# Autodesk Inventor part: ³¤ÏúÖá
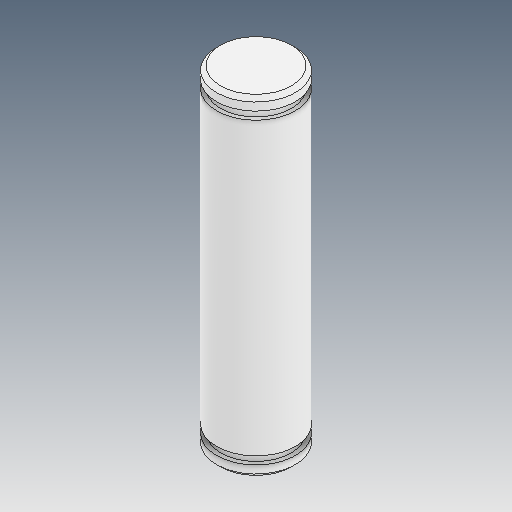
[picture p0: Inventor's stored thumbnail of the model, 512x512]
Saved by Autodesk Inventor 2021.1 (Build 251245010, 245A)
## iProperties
Created: 2021-05
Part Number: ³¤ÏúÖá
Material: Ogólny
Document SubType Name: Modeling
Designer: user
Density: 1 g/cm^3
Appearance: Domyślna
Author: user
Revision Number: ÈÎºÎ
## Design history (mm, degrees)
feature "ÊäÈë1"
node "Bryła1"
